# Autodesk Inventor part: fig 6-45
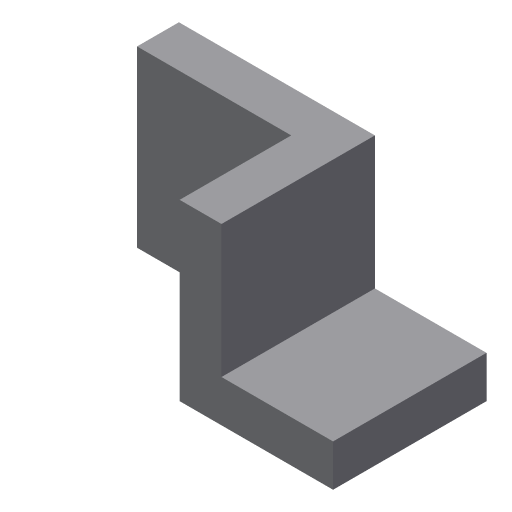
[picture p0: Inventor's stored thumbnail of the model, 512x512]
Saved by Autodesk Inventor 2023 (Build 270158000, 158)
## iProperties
Created: 2001-12
Part Number: fig 6-45
Document SubType Name: Modeling
Designer: Renu Muthoo
Density: 1 g/cm^3
Material: Generic
Appearance: Default
Control State: 0
Master: False
Checked Out: False
Shininess: 77.0
Angle Display Precision: 2
Document Length Units: 11269
Document Angle Units: 11279
Document Time Units: 11290
Document Mass Units: 11283
Document Length Units Precision: 3
Document Angle Units Precision: 2
Density: 0.0
Volumn: 0.0
Area: 0.0
PropertySet Name: Model Information
Author: Renu Muthoo
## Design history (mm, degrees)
node "Sketch1"
sketch "Sketch2"
  geometry: L1 (16.794, 27.142)-(16.794, -22.858); L2 (16.794, -22.858)-(-27.206, -22.858); L3 (-27.206, -22.858)-(-27.206, -10.858); L4 (-27.206, -10.858)-(4.794, -10.858); L5 (4.794, -10.858)-(4.794, 27.142); L6 (4.794, 27.142)-(16.794, 27.142)
  constraints: 12 end point, 4 parallel, 2 perpendicular, 1 vertical
  dimensions: "d0" = 44 distance of L1.end L2.end; "d1" = 50 distance of L1.start L1.end; "d2" = 12 distance of L2.end L3.end
extrude "Extrusion1" new body sketch "Sketch2" distance "d3" = 44; taper "d4" = 0 deg
sketch "Sketch4"
  geometry: L1 (-16.794, -27.142)-(-16.794, 22.858) reference; L2 (27.206, 22.858)-(27.206, 10.858) reference; L3 (-16.794, -27.142)-(-61.001, -27.142); L4 (-61.001, -27.142)-(-61.001, 22.858); L5 (-61.001, 22.858)-(-16.794, 22.858)
  constraints: 6 end point, 2 perpendicular, 1 parallel
extrude "Extrusion3" join sketch "Sketch4" distance "d13" = 12; taper "d14" = 0 deg
body "Solid1"
